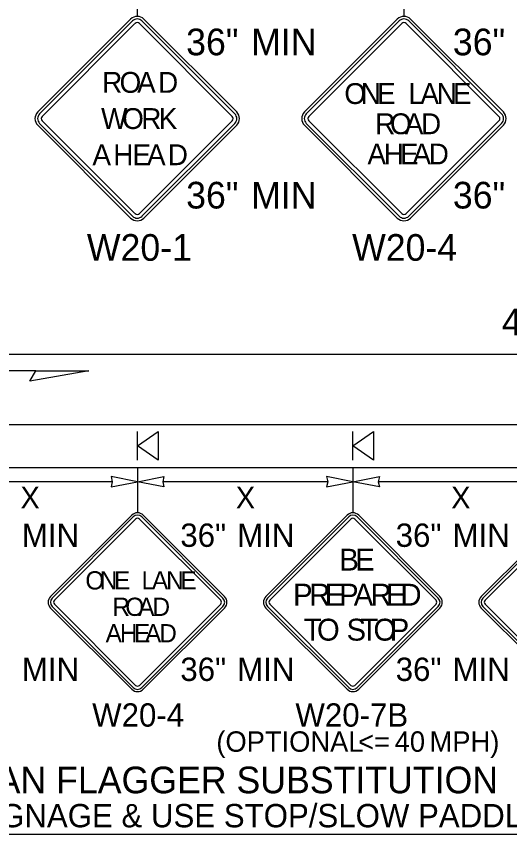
# Model space of a CAD drawing. Extents: x 99999.1 to 100095.7, y 99995 to 100010.7.
# Drawn here: x 100000.714 to 100002.194, y 100003.038 to 100005.492 of the extents above; entities that cross this region are included whole.
import ezdxf

# ---------------------------------------------------------------- set-up
doc = ezdxf.new("R2010")
doc.units = 0
for name, color, linetype in [('RD_ED_ShoulderPavedEdge', 7, 'Continuous'), ('RD_MK_LineEdgeWhite', 7, 'Continuous'), ('SH_DE_DetailHeading2Text', 7, 'Continuous'), ('TR_SN_ConstructionSigns', 7, 'Continuous'), ('TR_WZ_PortableSignMountBlk-Org', 7, 'Continuous'), ('TR_WZ_WorkZoneDetails', 7, 'Continuous'), ('TR_WZ_WorkZoneTextCurrent', 7, 'Continuous')]:
    doc.layers.add(name, color=color, linetype=linetype)

msp = doc.modelspace()

# ---------------------------------------------------------------- linework, layer by layer
at = {"layer": 'RD_ED_ShoulderPavedEdge'}
msp.add_line((100000.2089, 100004.1394), (100003.1825, 100004.1394), dxfattribs=at)
at = {"layer": 'RD_MK_LineEdgeWhite'}
msp.add_line((100000.2089, 100004.2685), (100003.1825, 100004.2685), dxfattribs=at)
at = {"layer": 'TR_SN_ConstructionSigns'}
for p, q in [((100001.0568, 100005.4841), (100000.7783, 100005.2057)), ((100001.375, 100005.2057), (100001.0965, 100005.4841)), ((100001.8568, 100005.4841), (100001.5783, 100005.2057)), ((100002.175, 100005.2057), (100001.8965, 100005.4841)), ((100001.0623, 100005.4786), (100000.7839, 100005.2001)), ((100000.7916, 100005.1924), (100001.07, 100005.4708)), ((100001.0833, 100005.4708), (100001.3617, 100005.1924)), ((100001.3694, 100005.2001), (100001.091, 100005.4786)), ((100001.8623, 100005.4786), (100001.5839, 100005.2001)), ((100001.5916, 100005.1924), (100001.87, 100005.4708)), ((100001.8833, 100005.4708), (100002.1617, 100005.1924)), ((100002.1694, 100005.2001), (100001.891, 100005.4786)), ((100000.7783, 100005.1659), (100001.0568, 100004.8875)), ((100000.7839, 100005.1714), (100001.0623, 100004.893)), ((100001.07, 100004.9007), (100000.7916, 100005.1792)), ((100001.3617, 100005.1792), (100001.0833, 100004.9007)), ((100001.091, 100004.893), (100001.3694, 100005.1714)), ((100001.0965, 100004.8875), (100001.375, 100005.1659)), ((100001.5783, 100005.1659), (100001.8568, 100004.8875)), ((100001.5839, 100005.1714), (100001.8623, 100004.893)), ((100001.87, 100004.9007), (100001.5916, 100005.1792)), ((100002.1617, 100005.1792), (100001.8833, 100004.9007)), ((100001.891, 100004.893), (100002.1694, 100005.1714)), ((100001.8965, 100004.8875), (100002.175, 100005.1659)), ((100001.0602, 100003.996), (100000.8166, 100003.7524)), ((100001.065, 100003.9912), (100000.8214, 100003.7476)), ((100001.3338, 100003.7476), (100001.0902, 100003.9912)), ((100001.3386, 100003.7524), (100001.095, 100003.996)), ((100001.7061, 100003.996), (100001.4625, 100003.7524)), ((100001.711, 100003.9912), (100001.4673, 100003.7476)), ((100001.9797, 100003.7476), (100001.7361, 100003.9912)), ((100001.9846, 100003.7524), (100001.7409, 100003.996)), ((100002.3521, 100003.996), (100002.1084, 100003.7524)), ((100002.3569, 100003.9912), (100002.1133, 100003.7476)), ((100000.8282, 100003.7408), (100001.0718, 100003.9844)), ((100001.0834, 100003.9844), (100001.327, 100003.7408)), ((100001.4741, 100003.7408), (100001.7177, 100003.9844)), ((100001.7293, 100003.9844), (100001.973, 100003.7408)), ((100002.12, 100003.7408), (100002.3637, 100003.9844)), ((100000.8166, 100003.7176), (100001.0602, 100003.474)), ((100000.8214, 100003.7224), (100001.065, 100003.4788)), ((100001.0718, 100003.4856), (100000.8282, 100003.7292)), ((100001.327, 100003.7292), (100001.0834, 100003.4856)), ((100001.0902, 100003.4788), (100001.3338, 100003.7224)), ((100001.095, 100003.474), (100001.3386, 100003.7176)), ((100001.4625, 100003.7176), (100001.7061, 100003.474)), ((100001.4673, 100003.7224), (100001.711, 100003.4788)), ((100001.7177, 100003.4856), (100001.4741, 100003.7292)), ((100001.973, 100003.7292), (100001.7293, 100003.4856)), ((100001.7361, 100003.4788), (100001.9797, 100003.7224)), ((100001.7409, 100003.474), (100001.9846, 100003.7176)), ((100002.1084, 100003.7176), (100002.3521, 100003.474)), ((100002.1133, 100003.7224), (100002.3569, 100003.4788)), ((100002.3637, 100003.4856), (100002.12, 100003.7292))]:
    msp.add_line(p, q, dxfattribs=at)
for centre, radius, start, end in [((100001.0767, 100005.4642), 0.0281, 45, 135), ((100001.0767, 100005.4642), 0.0203, 45, 135), ((100001.8767, 100005.4642), 0.0281, 45, 135), ((100001.8767, 100005.4642), 0.0203, 45, 135), ((100001.0767, 100005.4642), 0.00937, 45, 135), ((100001.8767, 100005.4642), 0.00937, 45, 135), ((100000.7982, 100005.1858), 0.0281, 135, 225), ((100000.7982, 100005.1858), 0.0203, 135, 225), ((100000.7982, 100005.1858), 0.00937, 135, 225), ((100001.3551, 100005.1858), 0.00937, 315, 45), ((100001.3551, 100005.1858), 0.0203, 315, 45), ((100001.3551, 100005.1858), 0.0281, 315, 45), ((100001.5982, 100005.1858), 0.0281, 135, 225), ((100001.5982, 100005.1858), 0.0203, 135, 225), ((100001.5982, 100005.1858), 0.00937, 135, 225), ((100002.1551, 100005.1858), 0.00937, 315, 45), ((100002.1551, 100005.1858), 0.0203, 315, 45), ((100002.1551, 100005.1858), 0.0281, 315, 45), ((100001.0767, 100004.9074), 0.00937, 225, 315), ((100001.8767, 100004.9074), 0.00937, 225, 315), ((100001.0767, 100004.9074), 0.0281, 225, 315), ((100001.0767, 100004.9074), 0.0203, 225, 315), ((100001.8767, 100004.9074), 0.0281, 225, 315), ((100001.8767, 100004.9074), 0.0203, 225, 315), ((100001.0776, 100003.9786), 0.0246, 45, 135), ((100001.0776, 100003.9786), 0.0178, 45, 135), ((100001.7235, 100003.9786), 0.0246, 45, 135), ((100001.7235, 100003.9786), 0.0178, 45, 135), ((100001.0776, 100003.9786), 0.0082, 45, 135), ((100001.7235, 100003.9786), 0.0082, 45, 135), ((100000.834, 100003.735), 0.0246, 135, 225), ((100000.834, 100003.735), 0.0178, 135, 225), ((100001.3212, 100003.735), 0.0178, 315, 45), ((100001.3212, 100003.735), 0.0246, 315, 45), ((100001.4799, 100003.735), 0.0246, 135, 225), ((100001.4799, 100003.735), 0.0178, 135, 225), ((100001.9672, 100003.735), 0.0178, 315, 45), ((100001.9672, 100003.735), 0.0246, 315, 45), ((100002.1258, 100003.735), 0.0246, 135, 225), ((100002.1258, 100003.735), 0.0178, 135, 225), ((100000.834, 100003.735), 0.0082, 135, 225), ((100001.3212, 100003.735), 0.0082, 315, 45), ((100001.4799, 100003.735), 0.0082, 135, 225), ((100001.9672, 100003.735), 0.0082, 315, 45), ((100002.1258, 100003.735), 0.0082, 135, 225), ((100001.0776, 100003.4914), 0.0246, 225, 315), ((100001.0776, 100003.4914), 0.0178, 225, 315), ((100001.0776, 100003.4914), 0.0082, 225, 315), ((100001.7235, 100003.4914), 0.0246, 225, 315), ((100001.7235, 100003.4914), 0.0178, 225, 315), ((100001.7235, 100003.4914), 0.0082, 225, 315)]:
    msp.add_arc(centre, radius, start, end, dxfattribs=at)
at = {"layer": 'TR_WZ_PortableSignMountBlk-Org'}
for p, q in [((100001.0776, 100004.1609), (100001.0776, 100004.247)), ((100001.7235, 100004.1609), (100001.7235, 100004.247))]:
    msp.add_line(p, q, dxfattribs=at)
for points in [[(100001.0776, 100004.2039), (100001.1395, 100004.247), (100001.1395, 100004.1609)], [(100001.7235, 100004.2039), (100001.7854, 100004.247), (100001.7854, 100004.1609)]]:
    msp.add_lwpolyline(points, close=True, dxfattribs=at)
at = {"layer": 'TR_WZ_WorkZoneDetails'}
for p, q in [((100001.0767, 100005.7326), (100001.0767, 100005.4923)), ((100001.8767, 100005.7323), (100001.8767, 100005.4923)), ((100000.7726, 100004.4292), (100000.578, 100004.4292)), ((100001.0776, 100004.1394), (100001.0776, 100004.0032)), ((100001.7235, 100004.1394), (100001.7235, 100004.0032)), ((100001.0019, 100004.0963), (100000.5073, 100004.0963)), ((100001.6479, 100004.0963), (100001.1533, 100004.0963)), ((100002.2938, 100004.0963), (100001.7992, 100004.0963))]:
    msp.add_line(p, q, dxfattribs=at)
for points in [[(100000.9313, 100004.4292), (100000.7546, 100004.3981), (100000.7726, 100004.4292)], [(100001.0776, 100004.0963), (100000.9982, 100004.1119), (100001.0019, 100004.0963), (100000.9982, 100004.0807)], [(100001.0776, 100004.0963), (100001.157, 100004.1119), (100001.1533, 100004.0963), (100001.157, 100004.0807)], [(100001.7235, 100004.0963), (100001.6442, 100004.1119), (100001.6479, 100004.0963), (100001.6442, 100004.0807)], [(100001.7235, 100004.0963), (100001.8029, 100004.1119), (100001.7992, 100004.0963), (100001.8029, 100004.0807)]]:
    msp.add_lwpolyline(points, close=True, dxfattribs=at)
at = {"layer": 'TR_WZ_WorkZoneTextCurrent'}
msp.add_lwpolyline([(100000.1, 100004.4792), (100003.2886, 100004.4792), (100003.2886, 100003.0379), (100000.1, 100003.0379)], close=True, dxfattribs=at)

# ---------------------------------------------------------------- texts
at = {"layer": 'SH_DE_DetailHeading2Text'}
msp.add_text('HUMAN FLAGGER SUBSTITUTION', height=0.08, rotation=360, dxfattribs=at).set_placement((100000.4115, 100003.1619))
at = {"layer": 'TR_SN_ConstructionSigns'}
for s, height, p in [('36"', 0.08, (100001.2234, 100005.3756)), ('MIN', 0.08, (100001.4184, 100005.3756)), ('36"', 0.08, (100002.0234, 100005.3756)), ('36"', 0.08, (100001.2234, 100004.916)), ('MIN', 0.08, (100001.4184, 100004.916)), ('36"', 0.08, (100002.0234, 100004.916)), ('W20-1', 0.08, (100000.9257, 100004.7592)), ('W20-4', 0.08, (100001.7212, 100004.7592)), ('40 MPH OR LESS', 0.08, (100002.1702, 100004.5352)), ('MIN', 0.07, (100000.7307, 100003.9011)), ('36"', 0.07, (100001.206, 100003.9011)), ('MIN', 0.07, (100001.3767, 100003.9011)), ('36"', 0.07, (100001.8519, 100003.9011)), ('MIN', 0.07, (100002.0226, 100003.9011)), ('36"', 0.07, (100001.206, 100003.4989)), ('36"', 0.07, (100001.8519, 100003.4989)), ('MIN', 0.07, (100000.7307, 100003.4989)), ('MIN', 0.07, (100001.3767, 100003.4989)), ('MIN', 0.07, (100002.0226, 100003.4989)), ('W20-4', 0.07, (100000.9416, 100003.3618)), ('W20-7B', 0.07, (100001.5512, 100003.3618)), ('(OPTIONAL', 0.06125, (100001.314, 100003.2865)), ('MPH)', 0.06125, (100001.9536, 100003.2865)), ('<=', 0.06125, (100001.7395, 100003.2865)), ('40', 0.06125, (100001.8489, 100003.2865))]:
    msp.add_text(s, height=height, rotation=360, dxfattribs=at).set_placement(p)
for s, height, p in [('R', 0.0625, (100000.9716, 100005.2631)), ('O', 0.0625, (100001.0237, 100005.2631)), ('A', 0.0625, (100001.0765, 100005.2631)), ('D', 0.0625, (100001.1392, 100005.2631)), ('O', 0.0625, (100001.6979, 100005.2295)), ('N', 0.0625, (100001.7473, 100005.2295)), ('E', 0.0625, (100001.796, 100005.2295)), ('L', 0.0625, (100001.8904, 100005.2295)), ('A', 0.0625, (100001.926, 100005.2295)), ('N', 0.0625, (100001.9748, 100005.2295)), ('E', 0.0625, (100002.0235, 100005.2295)), ('W', 0.0625, (100000.9683, 100005.1545)), ('O', 0.0625, (100001.0316, 100005.1545)), ('R', 0.0625, (100001.0888, 100005.1545)), ('K', 0.0625, (100001.1412, 100005.1545)), ('R', 0.0625, (100001.7904, 100005.1389)), ('O', 0.0625, (100001.8348, 100005.1389)), ('A', 0.0625, (100001.8792, 100005.1389)), ('D', 0.0625, (100001.9279, 100005.1389)), ('A', 0.0625, (100000.9423, 100005.046)), ('H', 0.0625, (100001.0048, 100005.046)), ('E', 0.0625, (100001.0623, 100005.046)), ('A', 0.0625, (100001.106, 100005.046)), ('D', 0.0625, (100001.1685, 100005.046)), ('A', 0.0625, (100001.7673, 100005.0483)), ('H', 0.0625, (100001.816, 100005.0483)), ('E', 0.0625, (100001.8648, 100005.0483)), ('A', 0.0625, (100001.9023, 100005.0483)), ('D', 0.0625, (100001.951, 100005.0483)), ('B', 0.0656, (100001.683, 100003.83)), ('E', 0.0656, (100001.7306, 100003.83)), ('O', 0.0547, (100000.9212, 100003.7733)), ('N', 0.0547, (100000.9644, 100003.7733)), ('E', 0.0547, (100001.0071, 100003.7733)), ('L', 0.0547, (100001.0896, 100003.7733)), ('A', 0.0547, (100001.1208, 100003.7733)), ('N', 0.0547, (100001.1635, 100003.7733)), ('E', 0.0547, (100001.2061, 100003.7733)), ('P', 0.0656, (100001.5442, 100003.7249)), ('R', 0.0656, (100001.5926, 100003.7249)), ('E', 0.0656, (100001.6391, 100003.7249)), ('P', 0.0656, (100001.6824, 100003.7249)), ('A', 0.0656, (100001.7261, 100003.7249)), ('R', 0.0656, (100001.7762, 100003.7249)), ('E', 0.0656, (100001.8228, 100003.7249)), ('D', 0.0656, (100001.8661, 100003.7249)), ('R', 0.0547, (100001.0021, 100003.694)), ('O', 0.0547, (100001.041, 100003.694)), ('A', 0.0547, (100001.0798, 100003.694)), ('D', 0.0547, (100001.1224, 100003.694)), ('A', 0.0547, (100000.9819, 100003.6147)), ('H', 0.0547, (100001.0246, 100003.6147)), ('E', 0.0547, (100001.0672, 100003.6147)), ('A', 0.0547, (100001.1, 100003.6147)), ('D', 0.0547, (100001.1427, 100003.6147)), ('T', 0.0656, (100001.5763, 100003.6199)), ('O', 0.0656, (100001.6158, 100003.6199)), ('S', 0.0656, (100001.7045, 100003.6199)), ('T', 0.0656, (100001.7458, 100003.6199)), ('O', 0.0656, (100001.7853, 100003.6199)), ('P', 0.0656, (100001.834, 100003.6199))]:
    msp.add_text(s, height=height, dxfattribs=at).set_placement(p)
at = {"layer": 'TR_WZ_WorkZoneTextCurrent'}
for s, height, p in [('X', 0.0646, (100000.7266, 100004.0166)), ('X', 0.0646, (100001.3725, 100004.0166)), ('X', 0.0646, (100002.0185, 100004.0166)), ('UPDATE SIGNAGE & USE STOP/SLOW PADDLE', 0.07, (100000.1713, 100003.0599))]:
    msp.add_text(s, height=height, dxfattribs=at).set_placement(p)

doc.saveas('drawing.dxf')
